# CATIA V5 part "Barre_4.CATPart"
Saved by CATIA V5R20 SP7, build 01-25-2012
Part number: Barre_4
Material "Acajou": density 600 kg/m3, Young's modulus 1.7e+10 Pa
Bounding box of the stored display mesh (mm): x -2 to 4, y -0.997 to 10.105, z -0.997 to 18.802
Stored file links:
  J:\IFMA\IAO\système avant mef\Barre_4.CATPart
  C:\Appli\Dassault Systemes\B20\intel_a\startup\materials\French\Catalog.CATMaterial
  C:\Appli\Dassault Systemes\B20\intel_a\startup\materials\mahogany.jpg
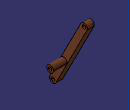
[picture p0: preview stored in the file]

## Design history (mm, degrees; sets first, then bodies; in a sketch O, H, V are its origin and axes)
Body1 (main body), material "Acajou"
  Plane1: stored without definition
  Point1 "Point.F": stored without definition
  Point2 "Point.S": stored without definition
  Sketch1 on Plane1, origin (-2, 0, 0), H (0, 1, 0), V (0, 0, 1)
    construction line L1 (0, 0) -> (9.1081, 17.8057)
    point P1 (0, 0)
    point P2 (9.1081, 17.8057)
    line L2 (-0.8903, 0.4554) -> (8.2178, 18.2611)
    line L3 (9.9984, 17.3503) -> (0.8903, -0.4554)
    arc A1 centre (9.1081, 17.8057) radius 1 from (8.2178, 18.2611) to (9.9984, 17.3503) cw
    arc A2 centre (0, 0) radius 1 from (0.8903, -0.4554) to (-0.8903, 0.4554) cw
    reference projected point E1 (0, 0) from Point1
    reference projected point E2 (9.1081, 17.8057) from Point2
    distance L1 L2 = 1
    tangency: A1 L2, A2 L2, A1 L3, A2 L3
    coincidence: P1 E1, P2 E2
  Pad1: profile Sketch1, direction (1, 0, 0), length 2
  Point3 "Point.D": stored without definition
  Sketch2 on yz-plane, origin (0, 0, 0), H (0, 1, 0), V (0, 0, 1)
    circle A1 centre (3.1651, 6.1875) radius 1
    point P1 (3.1651, 6.1875)
    reference projected point E1 (3.1651, 6.1875) from Point3
    radius A1 = 1
    coincidence: P1 E1
  Pad2: profile Sketch2, direction (1, 0, 0), length 4
  Sketch3 on start face of Pad1, origin (-2, 4.6023, 8.2804), H (0, 1, 0), V (0, 0, -1)
    point P1 (-4.6023, 8.2804)
    reference projected point E1 (-4.6023, 8.2804) from Point4
    coincidence: P1 E1
  Hole1: placed by Sketch3, at (-2, 0, 0) direction (1, 0, 0), diameter 1, through (limit type 3)
  Sketch4 on start face of Pad1, origin (-2, 5.5224, 9.7775), H (0, 1, 0), V (0, 0, -1)
    point P1 (-2.3574, 3.5901)
    reference projected point E1 (-2.3574, 3.5901) from Point5
    coincidence: P1 E1
  Hole2: placed by Sketch4, at (-2, 3.1651, 6.1875) direction (1, 0, 0), diameter 1, through (limit type 3)
  Sketch5 on start face of Pad1, origin (-2, 7.5135, 13.6241), H (0, 1, 0), V (0, 0, -1)
    point P1 (1.5946, -4.1816)
    reference projected point E1 (1.5946, -4.1816) from Point6
    coincidence: P1 E1
  Hole3: placed by Sketch5, at (-2, 9.1081, 17.8057) direction (1, 0, 0), diameter 1, through (limit type 3)
  Point4 "Point.F": stored without definition
  Point5 "Point.D": stored without definition
  Point6 "Point.S": stored without definition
